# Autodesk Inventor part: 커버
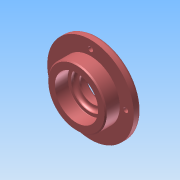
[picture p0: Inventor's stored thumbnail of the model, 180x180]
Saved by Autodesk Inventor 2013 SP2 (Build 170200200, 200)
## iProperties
Created: 2026-07
Part Number: 커버
Material: Generic
Document SubType Name: Modeling
Designer: aa
Density: 1 g/cm^3
변환 표준: STEP AP214IS
전처리기: Build: 200, Release: 2013 SP2 Update 6 - Date: Thu 07/17/2014
전송 단위: 밀리미터
불확실성: 0.01
Author: aa
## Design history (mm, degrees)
node "커버1"
node "솔리드1"
node "기준1"
